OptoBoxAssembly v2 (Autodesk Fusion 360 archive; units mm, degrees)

design "Arduino" references "Opto_Box_v2.f3d"
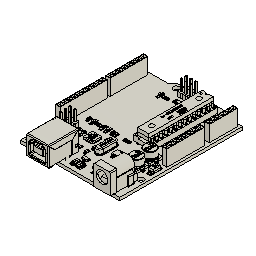
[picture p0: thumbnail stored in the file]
external_derived "ExternalDerived1" bodies "Body1", "Body1 (1)", "Body2", "Body1 (2)", "Body1 (3)", "Body1 (4)", "Body1 (5)", "Body1 (6)"
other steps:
derived_base_feature "Derived Base Feature1" bodies "Body1"
derived_base_feature "Derived Base Feature2" bodies "Body1 (1)", "Body2"
derived_base_feature "Derived Base Feature3" bodies "Body1 (2)"
derived_base_feature "Derived Base Feature4" bodies "Body1 (3)"
derived_base_feature "Derived Base Feature5" bodies "Body1 (4)"
derived_base_feature "Derived Base Feature6" bodies "Body1 (5)"
derived_base_feature "Derived Base Feature7" bodies "Body1 (6)"
derived_base_feature "Derived Base Feature8" bodies "Body1 (7)"
derived_base_feature "Derived Base Feature9" bodies "Body1 (8)", "Body2 (1)"
derived_base_feature "Derived Base Feature10" bodies "Body1 (9)", "Body2 (2)"
derived_base_feature "Derived Base Feature11" bodies "Body1 (10)"
derived_base_feature "Derived Base Feature12" bodies "Body1 (11)"
derived_base_feature "Derived Base Feature13" bodies "Body1 (12)"
derived_base_feature "Derived Base Feature14" bodies "Body1 (13)", "Body2 (3)"
derived_base_feature "Derived Base Feature15" bodies "Body1 (14)"
derived_base_feature "Derived Base Feature16" bodies "Body1 (15)"
derived_base_feature "Derived Base Feature17" bodies "Body1 (16)"
derived_base_feature "Derived Base Feature18" bodies "Body1 (17)"
derived_base_feature "Derived Base Feature19" bodies "Body1 (18)"
derived_base_feature "Derived Base Feature20" bodies "Body1 (19)"
derived_base_feature "Derived Base Feature21" bodies "Body1 (20)"
derived_base_feature "Derived Base Feature22" bodies "Body1 (21)"
derived_base_feature "Derived Base Feature23" bodies "Body1 (22)"
derived_base_feature "Derived Base Feature24" bodies "Body1 (23)"
derived_base_feature "Derived Base Feature25" bodies "Body1 (24)"
derived_base_feature "Derived Base Feature26" bodies "Body1 (25)"
derived_base_feature "Derived Base Feature27" bodies "Body1 (26)"
derived_base_feature "Derived Base Feature28" bodies "Body1 (27)"
derived_base_feature "Derived Base Feature29" bodies "Body1 (28)"
derived_base_feature "Derived Base Feature30" bodies "Body1 (29)"
derived_base_feature "Derived Base Feature31" bodies "Body1 (30)"
derived_base_feature "Derived Base Feature32" bodies "Body1 (31)"
derived_base_feature "Derived Base Feature33" bodies "Body1 (32)"
derived_base_feature "Derived Base Feature34" bodies "Body1 (33)"
derived_base_feature "Derived Base Feature35" bodies "Body1 (34)"
derived_base_feature "Derived Base Feature36" bodies "Body1 (35)"
derived_base_feature "Derived Base Feature37" bodies "Body1 (36)"
derived_base_feature "Derived Base Feature38" bodies "Body1 (37)"
derived_base_feature "Derived Base Feature39" bodies "Body1 (38)"
derived_base_feature "Derived Base Feature40" bodies "Body1 (39)"
derived_base_feature "Derived Base Feature41" bodies "Body1 (40)"
derived_base_feature "Derived Base Feature42" bodies "Body1 (41)"
derived_base_feature "Derived Base Feature43" bodies "Body1 (42)"
derived_base_feature "Derived Base Feature44" bodies "Body1 (43)"
derived_base_feature "Derived Base Feature45" bodies "Body1 (44)"
derived_base_feature "Derived Base Feature46" bodies "Body1 (45)"
derived_base_feature "Derived Base Feature47" bodies "Body1 (46)"
derived_base_feature "Derived Base Feature48" bodies "Body1 (47)"
derived_base_feature "Derived Base Feature49" bodies "Body1 (48)"
derived_base_feature "Derived Base Feature50" bodies "Body1 (49)", "Body2 (4)"
derived_base_feature "Derived Base Feature51" bodies "Body1 (50)", "Body2 (5)"
derived_base_feature "Derived Base Feature52" bodies "Body1 (51)", "Body2 (6)"
derived_base_feature "Derived Base Feature53" bodies "Body1 (52)"
derived_base_feature "Derived Base Feature54" bodies "Body1 (53)"
derived_base_feature "Derived Base Feature55" bodies "Body1 (54)"
derived_base_feature "Derived Base Feature56" bodies "Body1 (55)"
derived_base_feature "Derived Base Feature57"
derived_base_feature "Derived Base Feature58"
derived_base_feature "Derived Base Feature59"
derived_base_feature "Derived Base Feature60"
derived_base_feature "Derived Base Feature61"
derived_base_feature "Derived Base Feature62" bodies "Body1 (61)"
derived_base_feature "Derived Base Feature63" bodies "Body1 (62)", "Body2 (12)", "Body3 (5)", "Body4 (5)"
derived_base_feature "Derived Base Feature64" bodies "Body1 (63)"
derived_base_feature "Derived Base Feature65" bodies "Body1 (64)"
derived_base_feature "Derived Base Feature66" bodies "Body1 (65)"
derived_base_feature "Derived Base Feature67" bodies "Body1 (66)"
derived_base_feature "Derived Base Feature68" bodies "Body1 (67)"
derived_base_feature "Derived Base Feature69" bodies "Body1 (68)"
derived_base_feature "Derived Base Feature70" bodies "Body1 (69)"
derived_base_feature "Derived Base Feature71" bodies "Body1 (70)"
derived_base_feature "Derived Base Feature72" bodies "Body1 (71)"
derived_base_feature "Derived Base Feature73" bodies "Body1 (72)"
derived_base_feature "Derived Base Feature74" bodies "Body1 (73)"
derived_base_feature "Derived Base Feature75" bodies "Body1 (74)"
derived_base_feature "Derived Base Feature76" bodies "Body1 (75)", "Body2 (13)", "Body3 (6)"
derived_base_feature "Derived Base Feature77" bodies "Body1 (76)", "Body2 (14)", "Body3 (7)"
derived_base_feature "Derived Base Feature78" bodies "Body1 (77)", "Body2 (15)", "Body3 (8)", "Body4 (8)"
derived_base_feature "Derived Base Feature79" bodies "Body1 (78)"
derived_base_feature "Derived Base Feature80" bodies "Body1 (79)"
derived_base_feature "Derived Base Feature81" bodies "Body1 (80)", "Body2 (16)", "Body3 (9)", "Body4 (9)"
derived_base_feature "Derived Base Feature82" bodies "Body1 (81)", "Body2 (17)", "Body3 (10)", "Body4 (10)"
derived_base_feature "Derived Base Feature83" bodies "Body1 (82)", "Body2 (18)"
derived_base_feature "Derived Base Feature84" bodies "Body1 (83)"
named bodies: "Body1", "Body1 (1)", "Body2", "Body1 (2)", "Body1 (3)", "Body1 (4)", "Body1 (5)", "Body1 (6)", "Body1 (7)", "Body1 (8)", "Body2 (1)", "Body1 (9)", "Body2 (2)", "Body1 (10)", "Body1 (11)", "Body1 (12)", "Body1 (13)", "Body2 (3)", "Body1 (14)", "Body1 (15)", "Body1 (16)", "Body1 (17)", "Body1 (18)", "Body1 (19)", "Body1 (20)", "Body1 (21)", "Body1 (22)", "Body1 (23)", "Body1 (24)", "Body1 (25)", "Body1 (26)", "Body1 (27)", "Body1 (28)", "Body1 (29)", "Body1 (30)", "Body1 (31)", "Body1 (32)", "Body1 (33)", "Body1 (34)", "Body1 (35)", "Body1 (36)", "Body1 (37)", "Body1 (38)", "Body1 (39)", "Body1 (40)", "Body1 (41)", "Body1 (42)", "Body1 (43)", "Body1 (44)", "Body1 (45)", "Body1 (46)", "Body1 (47)", "Body1 (48)", "Body1 (49)", "Body2 (4)", "Body1 (50)", "Body2 (5)", "Body1 (51)", "Body2 (6)", "Body1 (52)"

design "WS2812-8"
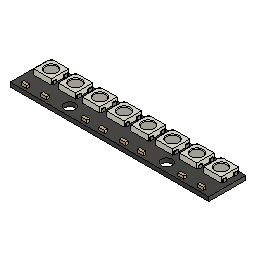
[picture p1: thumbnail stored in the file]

design "Opto_Box_v2_Top_Cover.f3d"
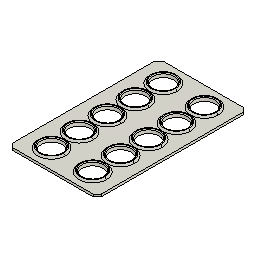
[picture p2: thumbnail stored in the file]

design "GUNCAIZHU_Fan DC brushless_30x30x8_5V"
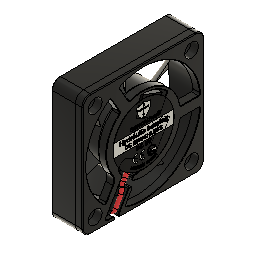
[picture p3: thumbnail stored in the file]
description: CATIA V5 STEP Exchange
part number: GUNCAIZHU_Fan DC brushless_30x30x8_5V

design "BN 661 1250809 cross recessed flat countersunk head screw M4x12"
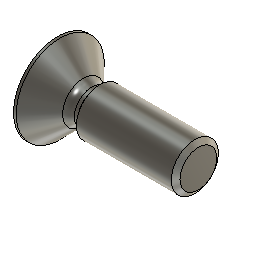
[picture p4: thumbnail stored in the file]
description: BN 661 1250809 cross recessed flat countersunk head screw M4x12
part number: BN 661 1250809 cross recessed flat countersunk head screw M4x12

design "Opto_Box_v2_Enclosure.f3d"
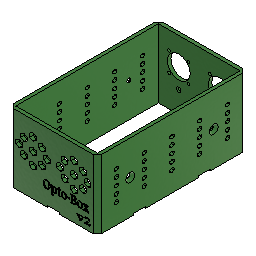
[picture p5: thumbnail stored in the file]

design "Opto_Box_v2_LightFixture_L.f3d"
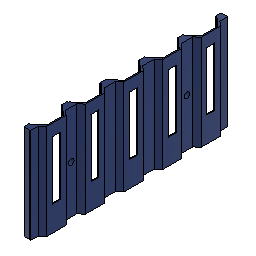
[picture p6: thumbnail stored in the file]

design "Opto_Box_v2.f3d" references "arduino uno"
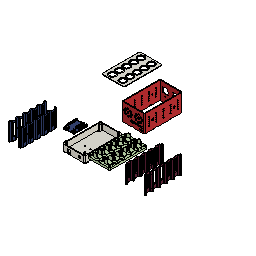
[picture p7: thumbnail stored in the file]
description: BN 1036 1385542 Gewindeeinsatz zum Einlegen B-M4
part number: BN 1036 1385542 Gewindeeinsatz zum Einlegen B-M4
description: BN 661 1250809 cross recessed flat countersunk head screw M4x12
part number: BN 661 1250809 cross recessed flat countersunk head screw M4x12

design "Opto_Box_v2_Bottom.f3d"
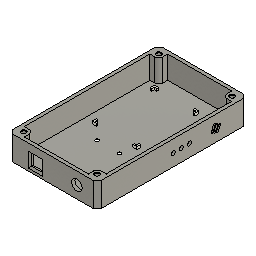
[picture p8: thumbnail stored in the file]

design "Opto_Box_v2_Mid_Section.f3d"
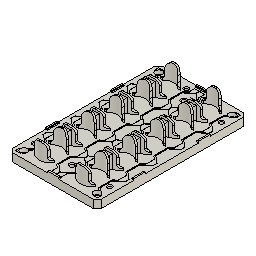
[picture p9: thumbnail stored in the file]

design "Opto_Box_v2LightFixture_R.f3d"
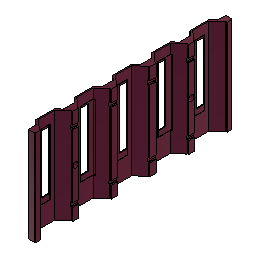
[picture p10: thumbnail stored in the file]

design "arduino uno"
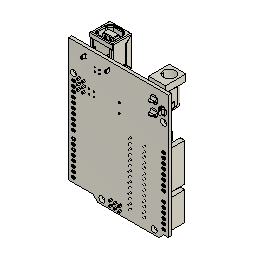
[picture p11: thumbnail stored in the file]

design "Opto_Box_v2_Foot_Pad.f3d"
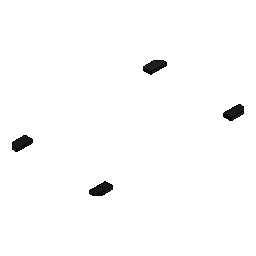
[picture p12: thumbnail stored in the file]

design "BN 1036 1385542 Gewindeeinsatz zum Einlegen B-M4"
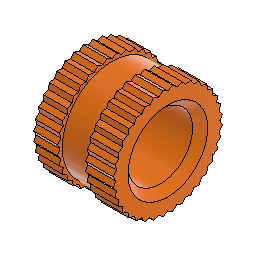
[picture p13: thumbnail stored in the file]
description: BN 1036 1385542 Gewindeeinsatz zum Einlegen B-M4
part number: BN 1036 1385542 Gewindeeinsatz zum Einlegen B-M4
